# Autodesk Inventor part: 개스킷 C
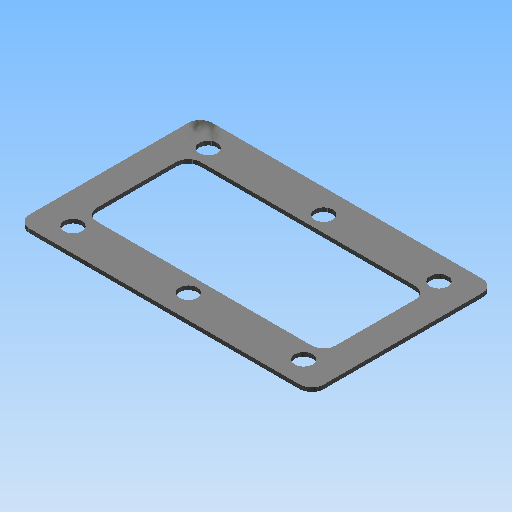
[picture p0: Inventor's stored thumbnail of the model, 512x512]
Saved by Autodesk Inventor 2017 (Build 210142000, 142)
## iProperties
Created: 2020-04
Part Number: 개스킷 C
Material: 고무
Document SubType Name: Modeling
Designer: mduedu
Density: 1 g/cm^3
Appearance: 고무 - 검은색 - 버전 1.1
Author: mduedu
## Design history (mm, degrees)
sketch "스케치1"
  geometry: L1 (37, 23)-(-37, 23); L2 (-37, 23)-(-37, -23); L3 (-37, -23)-(37, -23); L4 (37, -23)-(37, 23); L5 (37, 23)-(-37, -23); L6 (-37, 23)-(37, -23); L7 (30, 13)-(-30, 13); L8 (-30, 13)-(-30, -13); L9 (-30, -13)-(30, -13); L10 (30, -13)-(30, 13); L11 (30, 13)-(-30, -13); L12 (-30, 13)-(30, -13); 1 further point
  constraints: 24 end point, 4 midpoint, 4 parallel, 2 horizontal, 2 perpendicular
  dimensions: "d0" = 74 distance of L3.end L2.end; "d1" = 46 distance of L2.end L1.end; "d2" = 60 distance of L9.end L8.end; "d3" = 26 distance of L8.end L7.end
extrude "돌출1" new body sketch "스케치1" distance "d4" = 1; taper "d5" = 0 deg
fillet "모깎기1" dims "d6" = 3
fillet "모깎기2" dims "d7" = 3
sketch "스케치2"
  geometry: L1 (-29, -17)-(29, -17); L2 (29, -17)-(29, 17); L3 (29, 17)-(-29, 17); L4 (-29, 17)-(-29, -17); L5 (-29, -17)-(29, 17); L6 (29, -17)-(-29, 17); 7 further points
  constraints: 12 end point, 4 coincident, 4 midpoint, 2 parallel, 1 horizontal, 1 perpendicular
  dimensions: "d8" = 58 distance of L3.end L2.end; "d9" = 34 distance of L2.end L1.end
hole "구멍1" sketch "스케치2" at (-29, 17), (29, 17), (29, -17), (-29, -17), (0, 17), (0, -17) diameter "d10" = 4.5; stored, may be unused: countersink angle "d14" = 90 deg, drill point angle "d16" = 118 deg; dims "d11" = 6, "d12" = 4, "d13" = 2, "d15" = 8
node "솔리드1"
